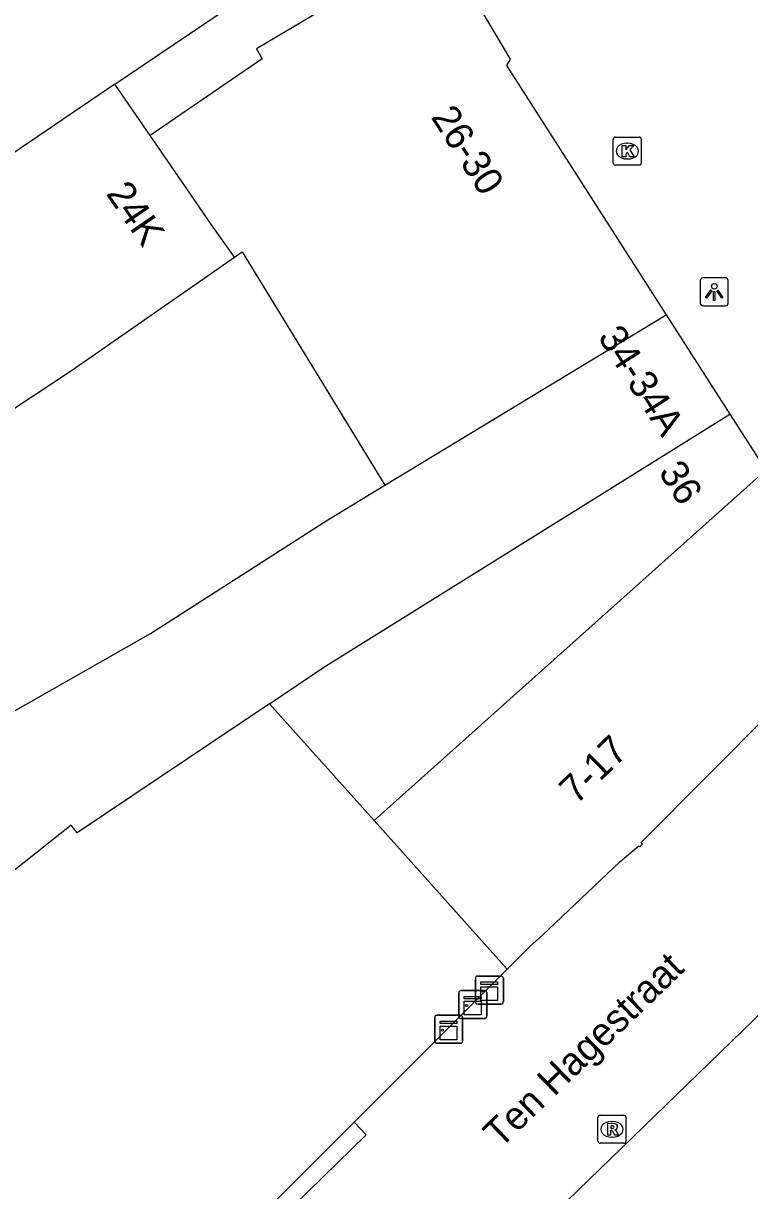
# Model space of a CAD drawing. Extents: x 161087 to 161922, y 382574 to 383873.
# Drawn here: x 161428.12 to 161454.07, y 383162.97 to 383204.67 of the extents above; entities that cross this region are included whole.
import ezdxf

# ---------------------------------------------------------------- set-up
doc = ezdxf.new("R2010")
doc.units = 0
for name, color, linetype in [('IMGEO_Kast', 7, 'Continuous'), ('IMGEO_Kolk', 7, 'Continuous'), ('IMGEO_Lichtpunt', 7, 'Continuous'), ('IMGEO_Openbare_ruimte_label', 7, 'Continuous'), ('IMGEO_Pand', 7, 'Continuous'), ('IMGEO_Pand_nummerreeks', 7, 'Continuous'), ('IMGEO_Rioolput', 7, 'Continuous'), ('IMGEO_Voetgangersgebied_gesloten', 7, 'Continuous'), ('IMGEO_Voetgangersgebied_open', 7, 'Continuous')]:
    doc.layers.add(name, color=color, linetype=linetype)

msp = doc.modelspace()

# ---------------------------------------------------------------- linework, layer by layer
at = {"layer": 'IMGEO_Kast'}
for p, q in [((161444.268, 383169.708), (161444.268, 383170.549)), ((161444.268, 383170.549), (161444.268, 383169.708)), ((161444.343, 383170.633), (161445.184, 383170.633)), ((161445.184, 383170.633), (161444.343, 383170.633)), ((161445.268, 383170.558), (161445.268, 383169.717)), ((161445.268, 383169.717), (161445.268, 383170.558)), ((161443.679, 383169.195), (161443.679, 383170.036)), ((161443.679, 383170.036), (161443.679, 383169.195)), ((161443.754, 383170.12), (161444.595, 383170.12)), ((161444.595, 383170.12), (161443.754, 383170.12)), ((161444.679, 383170.045), (161444.679, 383169.204)), ((161444.679, 383169.204), (161444.679, 383170.045)), ((161445.193, 383169.633), (161444.352, 383169.633)), ((161444.352, 383169.633), (161445.193, 383169.633)), ((161442.815, 383168.31), (161442.815, 383169.151)), ((161442.815, 383169.151), (161442.815, 383168.31)), ((161442.89, 383169.235), (161443.731, 383169.235)), ((161443.731, 383169.235), (161442.89, 383169.235)), ((161444.604, 383169.12), (161443.763, 383169.12)), ((161443.763, 383169.12), (161444.604, 383169.12)), ((161443.815, 383169.16), (161443.815, 383168.319)), ((161443.815, 383168.319), (161443.815, 383169.16)), ((161443.74, 383168.235), (161442.899, 383168.235)), ((161442.899, 383168.235), (161443.74, 383168.235))]:
    msp.add_line(p, q, dxfattribs=at)
for points in [[(161444.463, 383170.423), (161445.063, 383170.423), (161445.063, 383170.338), (161444.463, 383170.338), (161444.463, 383170.423)], [(161444.463, 383170.248), (161445.063, 383170.248), (161445.063, 383169.759), (161444.463, 383169.759), (161444.463, 383170.248)], [(161443.874, 383169.91), (161444.474, 383169.91), (161444.474, 383169.825), (161443.874, 383169.825), (161443.874, 383169.91)], [(161443.874, 383169.735), (161444.474, 383169.735), (161444.474, 383169.246), (161443.874, 383169.246), (161443.874, 383169.735)], [(161443.01, 383169.025), (161443.61, 383169.025), (161443.61, 383168.94), (161443.01, 383168.94), (161443.01, 383169.025)], [(161443.01, 383168.85), (161443.61, 383168.85), (161443.61, 383168.361), (161443.01, 383168.361), (161443.01, 383168.85)]]:
    msp.add_lwpolyline(points, dxfattribs=at)
for centre in [(161444.547, 383170.097), (161443.958, 383169.584), (161443.094, 383168.699)]:
    msp.add_circle(centre, 0.0377, dxfattribs=at)
for centre, start, end in [((161444.346, 383170.555), 92.4484, 184.2845), ((161444.346, 383170.555), 92.4484, 184.2845), ((161445.19, 383170.555), 2.4484, 94.2845), ((161445.19, 383170.555), 2.4484, 94.2845), ((161443.757, 383170.042), 92.4484, 184.2845), ((161443.757, 383170.042), 92.4484, 184.2845), ((161444.601, 383170.042), 2.4484, 94.2845), ((161444.601, 383170.042), 2.4484, 94.2845), ((161444.346, 383169.711), 182.4484, 274.2845), ((161444.346, 383169.711), 182.4484, 274.2845), ((161445.19, 383169.711), 272.4484, 4.2845), ((161445.19, 383169.711), 272.4484, 4.2845), ((161442.893, 383169.157), 92.4484, 184.2845), ((161442.893, 383169.157), 92.4484, 184.2845), ((161443.757, 383169.198), 182.4484, 274.2845), ((161443.757, 383169.198), 182.4484, 274.2845), ((161443.737, 383169.157), 2.4484, 94.2845), ((161443.737, 383169.157), 2.4484, 94.2845), ((161444.601, 383169.198), 272.4484, 4.2845), ((161444.601, 383169.198), 272.4484, 4.2845), ((161442.893, 383168.313), 182.4484, 274.2845), ((161442.893, 383168.313), 182.4484, 274.2845), ((161443.737, 383168.313), 272.4484, 4.2845), ((161443.737, 383168.313), 272.4484, 4.2845)]:
    msp.add_arc(centre, 0.0779, start, end, dxfattribs=at)
at = {"layer": 'IMGEO_Kolk'}
for p, q in [((161449.195, 383199.68), (161449.195, 383200.532)), ((161449.27, 383200.606), (161450.122, 383200.606)), ((161450.196, 383200.532), (161450.196, 383199.68)), ((161449.683, 383200.386), (161449.708, 383200.386)), ((161450.122, 383199.606), (161449.27, 383199.606)), ((161449.706, 383199.826), (161449.681, 383199.826))]:
    msp.add_line(p, q, dxfattribs=at)
for points in [[(161449.195, 383199.68), (161449.195, 383200.532)], [(161449.27, 383200.606), (161450.122, 383200.606)], [(161450.196, 383200.532), (161450.196, 383199.68)], [(161449.516, 383200.306), (161449.639, 383200.306), (161449.639, 383200.155), (161449.769, 383200.306), (161449.933, 383200.306), (161449.787, 383200.155), (161449.94, 383199.906), (161449.788, 383199.906), (161449.703, 383200.07), (161449.639, 383200.003), (161449.639, 383199.906), (161449.516, 383199.906), (161449.516, 383200.306)], [(161450.122, 383199.606), (161449.27, 383199.606)]]:
    msp.add_lwpolyline(points, dxfattribs=at)
for centre, start, end in [((161449.272, 383200.53), 91.552, 178.448), ((161449.272, 383200.53), 91.552, 178.448), ((161450.12, 383200.53), 1.552, 88.448), ((161450.12, 383200.53), 1.552, 88.448), ((161449.272, 383199.682), 181.552, 268.448), ((161449.272, 383199.682), 181.552, 268.448), ((161450.12, 383199.682), 271.552, 358.448), ((161450.12, 383199.682), 271.552, 358.448)]:
    msp.add_arc(centre, 0.0765, start, end, dxfattribs=at)
for centre, major_axis, ratio, start_param, end_param in [((161449.682, 383200.106), (-0.387, 0.002), 0.722429, 4.712389, 7.853982), ((161449.707, 383200.106), (-0.39, 0.002), 0.717154, 1.570796, 4.712389)]:
    msp.add_ellipse(centre, major_axis=major_axis, ratio=ratio, start_param=start_param, end_param=end_param, dxfattribs=at)
at = {"layer": 'IMGEO_Lichtpunt'}
for p, q in [((161452.303, 383195.481), (161452.303, 383194.674)), ((161452.303, 383195.481), (161452.303, 383194.674)), ((161453.205, 383195.576), (161452.397, 383195.576)), ((161453.205, 383195.576), (161452.397, 383195.576)), ((161453.299, 383194.674), (161453.299, 383195.481)), ((161453.299, 383194.674), (161453.299, 383195.481)), ((161452.397, 383194.58), (161453.205, 383194.58)), ((161452.397, 383194.58), (161453.205, 383194.58))]:
    msp.add_line(p, q, dxfattribs=at)
for points in [[(161452.677, 383195.145), (161452.716, 383195.117), (161452.528, 383194.855), (161452.49, 383194.882), (161452.677, 383195.145)], [(161452.779, 383195.097), (161452.826, 383195.097), (161452.826, 383194.775), (161452.779, 383194.775), (161452.779, 383195.097)], [(161452.889, 383195.117), (161452.927, 383195.144), (161453.114, 383194.882), (161453.075, 383194.854), (161452.889, 383195.117)]]:
    msp.add_lwpolyline(points, dxfattribs=at)
msp.add_circle((161452.802, 383195.279), 0.0994, dxfattribs=at)
for centre, start, end in [((161452.397, 383195.481), 90, 180), ((161452.397, 383195.481), 90, 180), ((161453.205, 383195.481), 0, 90), ((161453.205, 383195.481), 0, 90), ((161452.397, 383194.674), 180, 270), ((161452.397, 383194.674), 180, 270), ((161453.205, 383194.674), 270, 0), ((161453.205, 383194.674), 270, 360)]:
    msp.add_arc(centre, 0.0946, start, end, dxfattribs=at)
at = {"layer": 'IMGEO_Pand'}
for points in [[(161431.392, 383202.5), (161437.784, 383206.826), (161441.924, 383209.628)], [(161443.003, 383207.636), (161438.699, 383205.093), (161436.447, 383203.762), (161436.657, 383203.407), (161432.647, 383200.664)], [(161443.003, 383207.636), (161445.509, 383203.396), (161445.379, 383203.166), (161451.081, 383194.26)], [(161431.392, 383202.5), (161420.673, 383195.221)], [(161432.647, 383200.664), (161431.392, 383202.5)], [(161435.66, 383196.32), (161434.844, 383197.469), (161433.784, 383199.027), (161432.647, 383200.664)], [(161409.541, 383175.571), (161412.051, 383177.785), (161421.262, 383186.163), (161424.769, 383188.921), (161429.848, 383192.27), (161435.66, 383196.32)], [(161435.66, 383196.32), (161435.941, 383196.513), (161438.158, 383192.886), (161441.04, 383188.172)], [(161441.04, 383188.172), (161451.081, 383194.26)], [(161451.081, 383194.26), (161453.355, 383190.709)], [(161436.915, 383180.365), (161438.823, 383181.646), (161453.355, 383190.709)], [(161453.355, 383190.709), (161454.639, 383188.704)], [(161454.639, 383188.704), (161440.649, 383176.193)], [(161414.477, 383170.051), (161424.686, 383178.334), (161432.665, 383182.874), (161439.003, 383186.937), (161441.04, 383188.172)], [(161445.404, 383170.879), (161446.229, 383171.704), (161446.667, 383172.091), (161449.429, 383174.715), (161450.105, 383175.285), (161450.138, 383175.248), (161450.242, 383175.342), (161450.195, 383175.406), (161457.228, 383182.482), (161457.325, 383182.581), (161457.301, 383182.611)], [(161436.915, 383180.365), (161430.051, 383175.757), (161429.835, 383176.029), (161417.719, 383166.415)], [(161440.649, 383176.193), (161436.915, 383180.365)], [(161440.649, 383176.193), (161445.404, 383170.879)], [(161439.944, 383165.418), (161444.895, 383170.37), (161445.404, 383170.879)], [(161439.944, 383165.418), (161439.853, 383165.327), (161430.737, 383156.206), (161429.871, 383155.63), (161428.844, 383155.439), (161427.82, 383155.684), (161426.984, 383156.288), (161423.41, 383160.052)]]:
    msp.add_lwpolyline(points, dxfattribs=at)
at = {"layer": 'IMGEO_Rioolput'}
for p, q in [((161448.648, 383164.736), (161448.648, 383165.588)), ((161448.723, 383165.662), (161449.575, 383165.662)), ((161449.136, 383165.442), (161449.161, 383165.442)), ((161449.649, 383165.588), (161449.649, 383164.736)), ((161449.575, 383164.662), (161448.723, 383164.662)), ((161449.159, 383164.882), (161449.134, 383164.882))]:
    msp.add_line(p, q, dxfattribs=at)
for points in [[(161448.648, 383164.736), (161448.648, 383165.588)], [(161448.723, 383165.662), (161449.575, 383165.662)], [(161449.649, 383165.588), (161449.649, 383164.736)], [(161449.237, 383165.36), (161448.985, 383165.362), (161448.985, 383164.962)], [(161448.985, 383164.962), (161449.109, 383164.962), (161449.109, 383165.124), (161449.12, 383165.124)], [(161449.163, 383165.281), (161449.109, 383165.281), (161449.109, 383165.2)], [(161449.109, 383165.2), (161449.161, 383165.2)], [(161449.167, 383165.095), (161449.238, 383164.962), (161449.378, 383164.962), (161449.313, 383165.088)], [(161449.575, 383164.662), (161448.723, 383164.662)]]:
    msp.add_lwpolyline(points, dxfattribs=at)
for centre, radius, start, end in [((161448.725, 383165.586), 0.0765, 91.552, 178.448), ((161448.725, 383165.586), 0.0765, 91.552, 178.448), ((161449.573, 383165.586), 0.0765, 1.552, 88.448), ((161449.573, 383165.586), 0.0765, 1.552, 88.448), ((161449.119, 383165.071), 0.0533, 26.0293, 88.6989), ((161449.145, 383165.389), 0.19, 274.7715, 282.9687), ((161449.169, 383165.185), 0.0964, 77.0061, 93.1865), ((161449.183, 383165.242), 0.0378, 276.6634, 79.6772), ((161449.236, 383165.25), 0.109, 350.3612, 89.416), ((161449.234, 383165.25), 0.112, 277.5842, 350.9817), ((161449.218, 383165.035), 0.108, 29.5134, 73.7905), ((161448.725, 383164.738), 0.0765, 181.552, 268.448), ((161448.725, 383164.738), 0.0765, 181.552, 268.448), ((161449.573, 383164.738), 0.0765, 271.552, 358.448), ((161449.573, 383164.738), 0.0765, 271.552, 358.448)]:
    msp.add_arc(centre, radius, start, end, dxfattribs=at)
for centre, major_axis, ratio, start_param, end_param in [((161449.135, 383165.162), (-0.387, 0.002), 0.722429, 4.712389, 7.853982), ((161449.16, 383165.162), (-0.39, 0.002), 0.717154, 1.570796, 4.712389)]:
    msp.add_ellipse(centre, major_axis=major_axis, ratio=ratio, start_param=start_param, end_param=end_param, dxfattribs=at)
at = {"layer": 'IMGEO_Voetgangersgebied_gesloten'}
msp.add_lwpolyline([(161433.223, 383150.013), (161439.743, 383155.034), (161465.512, 383180.027)], dxfattribs=at)
at = {"layer": 'IMGEO_Voetgangersgebied_open'}
msp.add_lwpolyline([(161431.056, 383155.861), (161440.372, 383164.968), (161439.944, 383165.418)], dxfattribs=at)

# ---------------------------------------------------------------- texts
at = {"layer": 'IMGEO_Openbare_ruimte_label'}
msp.add_text('Ten Hagestraat', height=1, rotation=44.0276, dxfattribs=at).set_placement((161445.156, 383164.443))
at = {"layer": 'IMGEO_Pand_nummerreeks'}
for s, rotation, p in [('26-30', 302.6293, (161442.661, 383201.326)), ('24K', 304.5835, (161431.053, 383198.586)), ('34-34A', 302.6355, (161448.621, 383193.465)), ('36', 302.6237, (161450.789, 383188.634)), ('7-17', 44.536, (161447.875, 383176.73))]:
    msp.add_text(s, height=1, rotation=rotation, dxfattribs=at).set_placement(p)

doc.saveas('drawing.dxf')
